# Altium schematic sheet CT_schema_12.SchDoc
size 385 x 278 mm
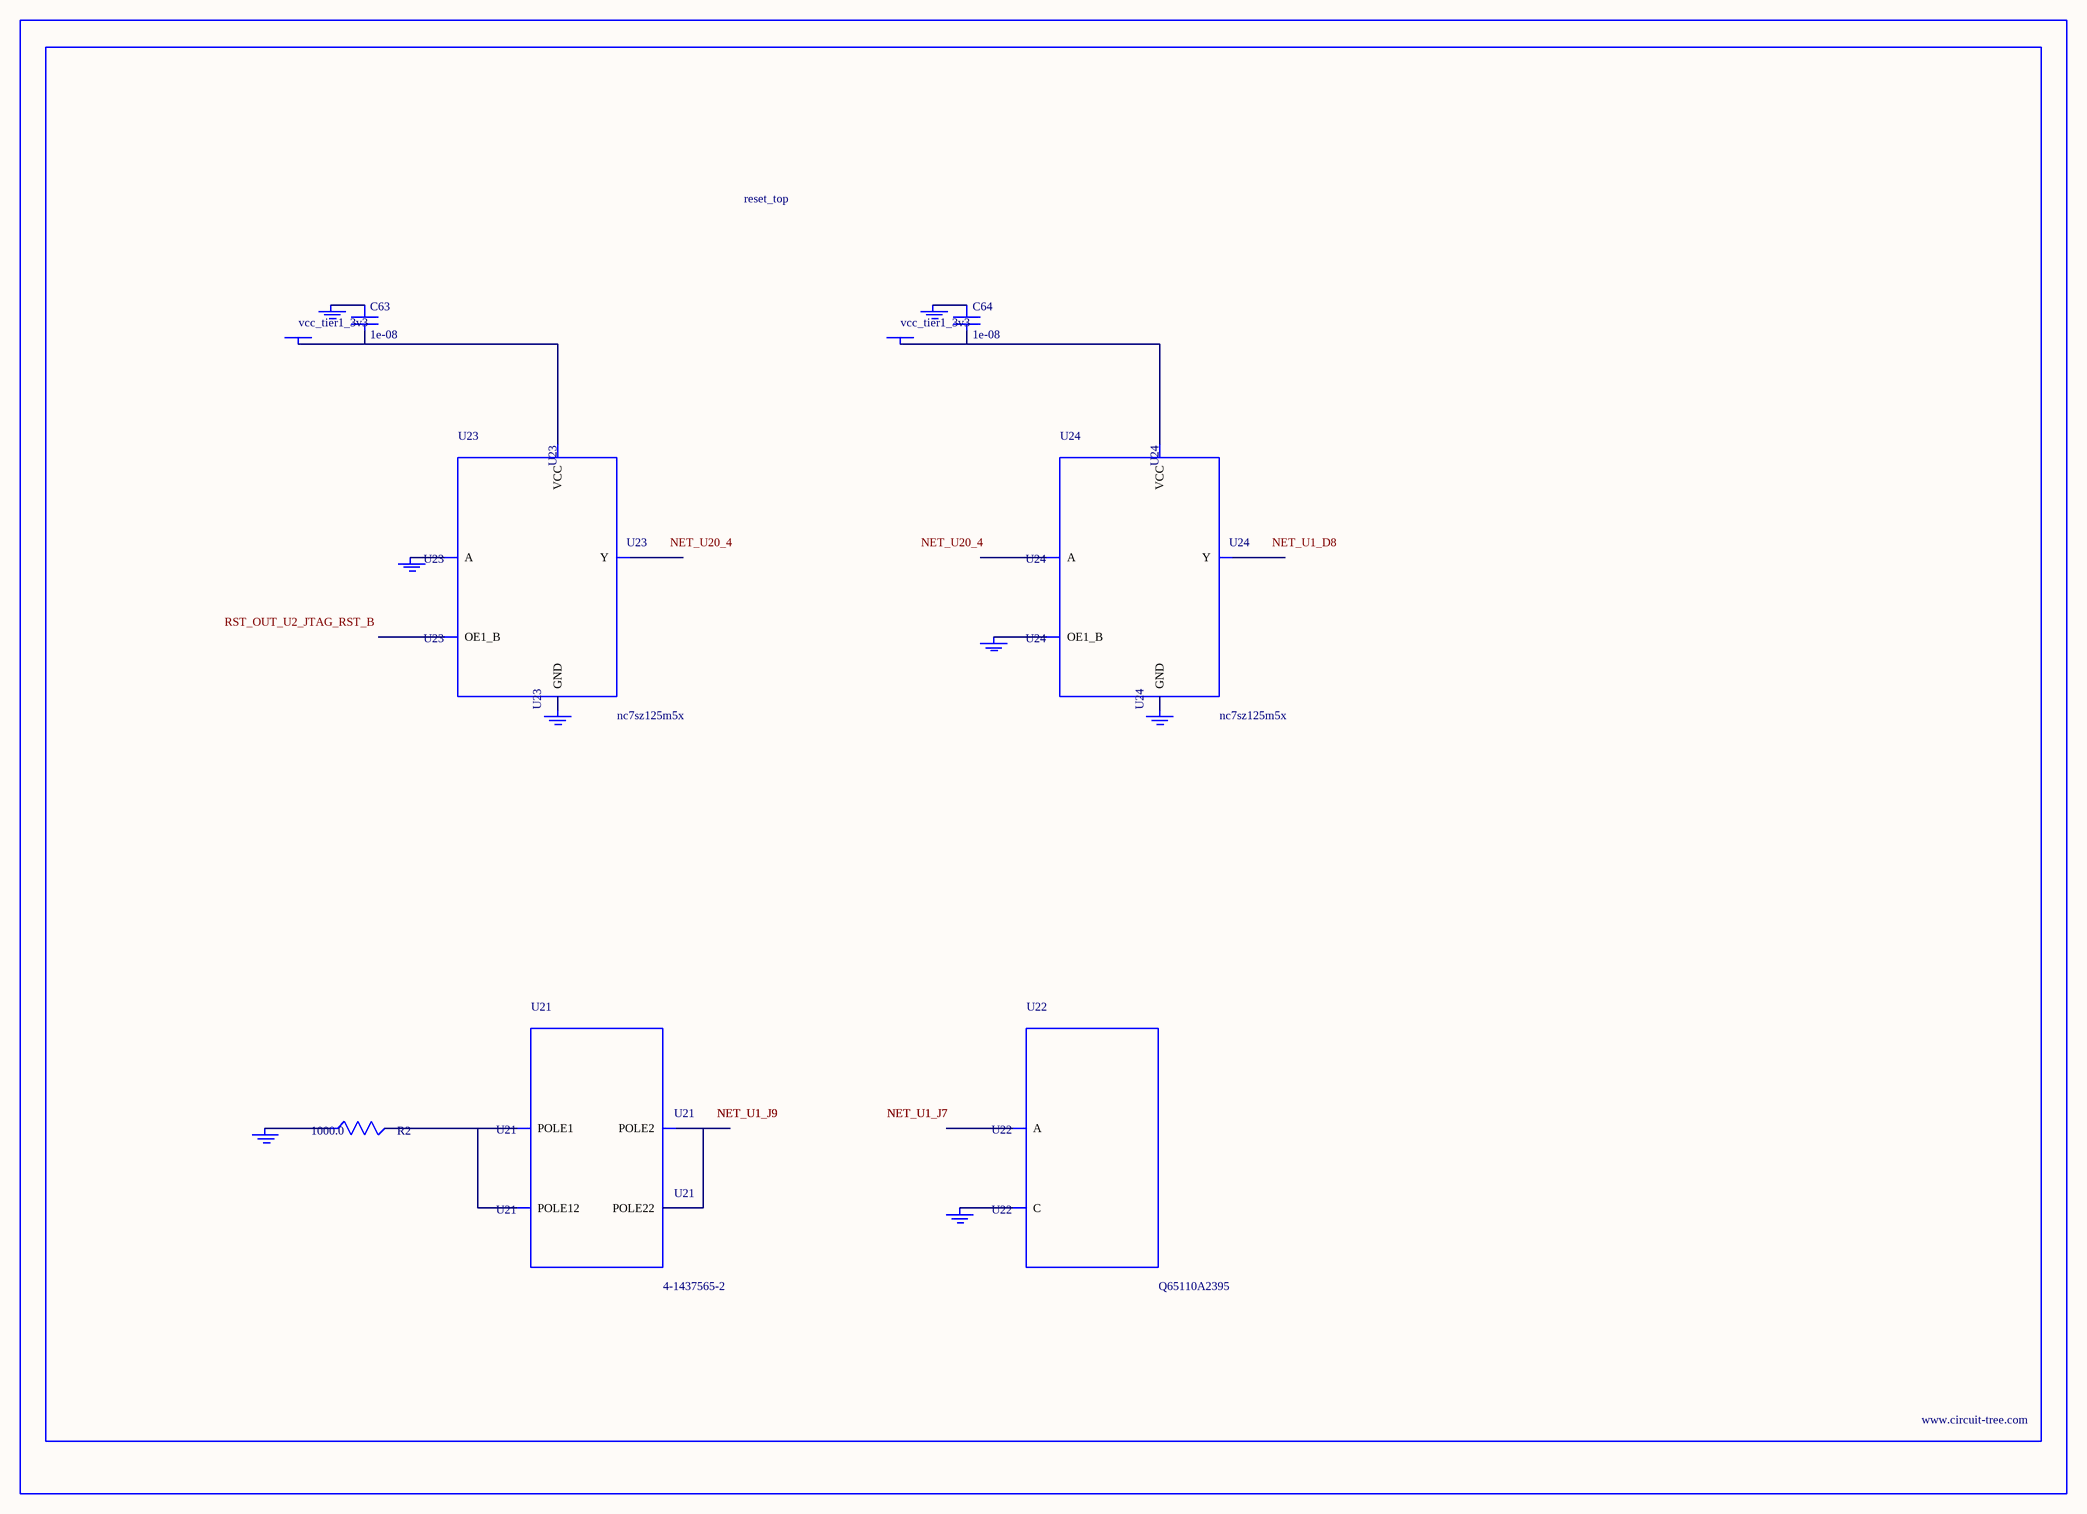
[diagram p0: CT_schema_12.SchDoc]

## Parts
BORDER11  (no value)
C63  1e-08  [C0402]
C64  1e-08  [C0402]
GND_INSTANCE_11_0  (no value)
GND_INSTANCE_11_1  (no value)
GND_INSTANCE_11_2  (no value)
GND_INSTANCE_11_3  (no value)
GND_INSTANCE_11_4  (no value)
GND_INSTANCE_11_5  (no value)
GND_INSTANCE_11_6  (no value)
GND_INSTANCE_11_7  (no value)
POWER_INSTANCE_11_0  vcc_tier1_3v3
POWER_INSTANCE_11_1  vcc_tier1_3v3
R2  1000.0  [R0603]
U21  4-1437565-2  [SW_4-1437565-2]
U22  Q65110A2395  [LGM67K-G1J2-24-Z]
U23  nc7sz125m5x  [NC7SZ125M5X]
U24  nc7sz125m5x  [NC7SZ125M5X]

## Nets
NetC63_1: C63.1 GND_INSTANCE_11_2.0(GND)
NetC63_2: C63.2 POWER_INSTANCE_11_0.0(PWR) U23.5(VCC)
NetC64_1: C64.1 GND_INSTANCE_11_5.0(GND)
NetC64_2: C64.2 POWER_INSTANCE_11_1.0(PWR) U24.5(VCC)
NetGND_INSTANCE_11_0_0: GND_INSTANCE_11_0.0(GND) R2.1
NetGND_INSTANCE_11_1_0: GND_INSTANCE_11_1.0(GND) U22.C
NetGND_INSTANCE_11_3_0: GND_INSTANCE_11_3.0(GND) U23.2(A)
NetGND_INSTANCE_11_4_0: GND_INSTANCE_11_4.0(GND) U23.3(GND)
NetGND_INSTANCE_11_6_0: GND_INSTANCE_11_6.0(GND) U24.1(OE1_B)
NetGND_INSTANCE_11_7_0: GND_INSTANCE_11_7.0(GND) U24.3(GND)
NetR2_2: R2.2 U21.1(POLE1) U21.2(POLE12)
NetU21_3: U21.3(POLE2) U21.4(POLE22)

Not connected (* = marked no-connect by the designer): U22 A; U23 1(OE1_B) 4(Y); U24 2(A) 4(Y)

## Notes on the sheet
- Labels drawn without touching a wire or pin: NET_U1_D8, NET_U20_4, RST_OUT_U2_JTAG_RST_B

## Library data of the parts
BORDER11 = BORDER_PAGE11
C63 C64 = C0402C103K3RAC
GND_INSTANCE_11_0-GND_INSTANCE_11_7 = GND
POWER_INSTANCE_11_0 POWER_INSTANCE_11_1 = PWR
R2 = RC0603JR-071KL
